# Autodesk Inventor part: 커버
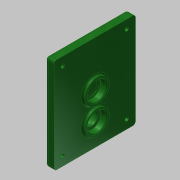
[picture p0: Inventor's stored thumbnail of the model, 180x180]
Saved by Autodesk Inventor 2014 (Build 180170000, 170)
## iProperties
Created: 2016-02
Part Number: 커버
Material: 알루미늄 6061
Document SubType Name: Modeling
Designer: mduedu
Density: 2.71 g/cm^3
Appearance: 매끄러움 - 짙은 산림 녹색
Author: mduedu
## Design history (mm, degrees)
sketch "스케치1"
  geometry: L1 (63, 47)-(-47, 47); L2 (-47, 47)-(-47, -47); L3 (-47, -47)-(63, -47); L4 (63, -47)-(63, 47); 2 further points
  constraints: 8 end point, 2 parallel, 1 horizontal, 1 horizontal alignment, 1 midpoint, 1 perpendicular
  dimensions: "d102" = 94 distance of L3.end L1.start; "d104" = 47 distance from line of L2 point (0, 0); "d105" = 110 distance of L1.start L1.end
extrude "돌출1" new body sketch "스케치1" distance "d1" = 10; taper "d2" = 0 deg
sketch "스케치2"
  geometry: C1 r 14 at (0, 11); 1 further point
  constraints: 1 centre point, 1 vertical alignment
  dimensions: "d3" = 28 diameter of C1; "d6" = 11 distance of C1.centre point (0, 0)
extrude "돌출2" join sketch "스케치2" distance "d7" = 3; taper "d8" = 0 deg
sketch "스케치3"
  geometry: C1 r 14 at (0, -20); 1 further point
  constraints: 1 centre point, 1 vertical alignment
  dimensions: "d9" = 28 diameter of C1; "d10" = 20 distance of C1.centre point (0, 0)
extrude "돌출3" join sketch "스케치3" distance "d11" = 3; taper "d12" = 0 deg
hole "구멍1" diameter "d15" = 22; stored, may be unused: countersink angle "d19" = 90 deg, drill point angle "d21" = 0 deg; dims "d13" = 10, "d14" = 10, "d16" = 6, "d17" = 4, "d18" = 2, "d20" = 7
hole "구멍2" diameter "d24" = 18; stored, may be unused: countersink angle "d28" = 90 deg, drill point angle "d30" = 0 deg; dims "d22" = 10, "d23" = 10, "d25" = 6, "d26" = 4, "d27" = 2, "d29" = 1
hole "구멍3" diameter "d33" = 22; stored, may be unused: countersink angle "d37" = 90 deg, drill point angle "d39" = 0 deg; dims "d34" = 6, "d35" = 4, "d36" = 2, "d38" = 7, "d73" = 10, "d74" = 10
sketch "스케치4"
  geometry: C1 r 14 at (0, -20) reference; C2 r 18 at (0, -20); 1 further point
  constraints: 1 centre point, 1 coincident
  dimensions: "d40" = 36 diameter of C2
extrude "돌출4" join sketch "스케치4" distance "d41" = 4; taper "d42" = 0 deg
hole "구멍4" diameter "d45" = 22; stored, may be unused: countersink angle "d49" = 90 deg, drill point angle "d51" = 0 deg; dims "d43" = 10, "d44" = 10, "d46" = 6, "d47" = 4, "d48" = 2, "d50" = 7
hole "구멍5" diameter "d54" = 15; stored, may be unused: countersink angle "d58" = 90 deg, drill point angle "d60" = 0 deg; dims "d52" = 10, "d53" = 10, "d55" = 6, "d56" = 4, "d57" = 2, "d59" = 7
fillet "모깎기1" dims "d61" = 0.3
fillet "모깎기2" dims "d62" = 2
chamfer "모따기1" distance "d63" = 1; stored, may be unused: second distance "d64" = 2, angle "d65" = 45 deg
fillet "모깎기6" dims "d88" = 2
fillet "모깎기4" dims "d75" = 2
sketch "스케치9"
  geometry: L1 (47, 63)-(47, -47) reference; L2 (-47, 63)-(47, 63) reference; L3 (-47, -47)-(-47, 63) reference; L4 (47, -47)-(-47, -47) reference; L5 (37, 53)-(37, -37); L6 (37, -37)-(-37, -37); L7 (-37, -37)-(-37, 53); L8 (-37, 53)-(37, 53); C1 r 20 at (0, -20) reference; 5 further points
  constraints: 8 end point, 4 coincident, 3 other
  dimensions: "d107" = 10 distance between parallel lines of L8 L2
hole "구멍7" sketch "스케치9" at (-37, 53), (37, 53), (37, -37), (-37, -37) diameter "d108" = 4.5; stored, may be unused: countersink angle "d112" = 90 deg, drill point angle "d114" = 118 deg; dims "d109" = 6, "d110" = 8, "d111" = 4.6, "d113" = 8
fillet "모깎기8" dims "d106" = 3
fillet "모깎기9" dims "d115" = 3
node "솔리드1"
node "투영된 루프2"
